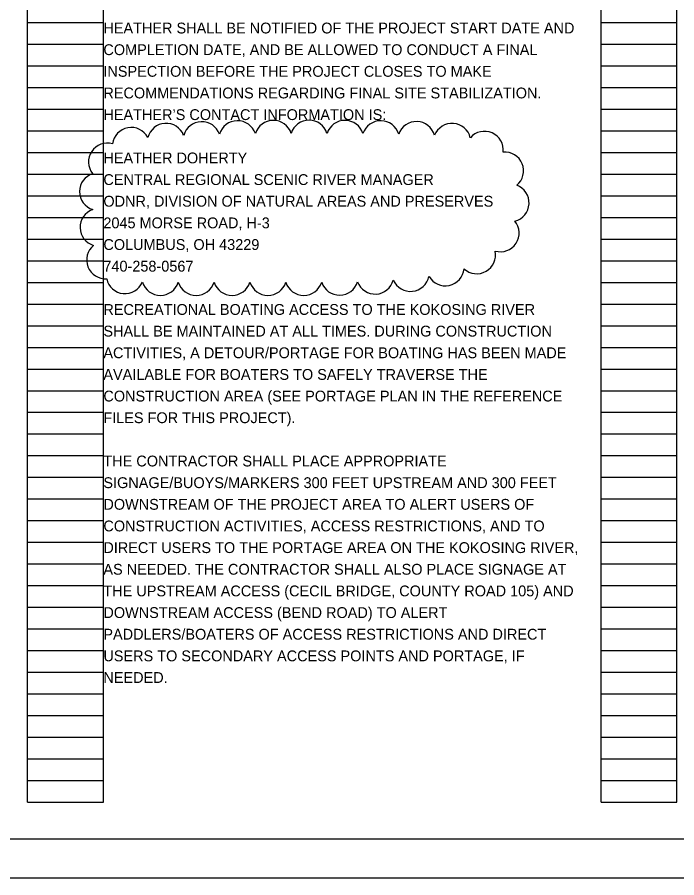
# Model space of a CAD drawing. Extents: x 0 to 58.9, y 0 to 22.
# Drawn here: x 16.12 to 24.66, y 0 to 11.13 of the extents above; entities that cross this region are included whole.
import ezdxf

# ---------------------------------------------------------------- set-up
doc = ezdxf.new("R2010")
doc.units = 0
for name, color, linetype in [('CS-ALGN-CNTR', 7, 'Continuous'), ('CS-ALGN-TEXT', 7, 'Continuous'), ('CS-ANNO-MATC', 7, 'Continuous'), ('CS-ANNO-MATC-MASK', 7, 'Continuous'), ('CS-ANNO-MATC-TEXT', 7, 'Continuous')]:
    doc.layers.add(name, color=color, linetype=linetype)

msp = doc.modelspace()

# ---------------------------------------------------------------- linework, layer by layer
at = {"layer": 'CS-ALGN-CNTR'}
msp.add_lwpolyline([(0, 0), (34, 0), (34, 22), (0, 22)], close=True, dxfattribs=at)
at = {"layer": 'CS-ALGN-TEXT'}
msp.add_lwpolyline([(1.5, 21.5), (33.5, 21.5), (33.5, 0.5), (1.5, 0.5)], close=True, dxfattribs=at)
at = {"layer": 'CS-ANNO-MATC-MASK'}
for p, q in [((16.26, 0.98), (16.26, 21.14)), ((17.24, 0.98), (17.24, 21.14)), ((23.68, 0.98), (23.68, 21.14)), ((24.66, 0.98), (24.66, 21.14)), ((16.26, 11.06), (17.24, 11.06)), ((23.68, 11.06), (24.66, 11.06)), ((16.26, 10.78), (17.24, 10.78)), ((23.68, 10.78), (24.66, 10.78)), ((16.26, 10.5), (17.24, 10.5)), ((23.68, 10.5), (24.66, 10.5)), ((16.26, 10.22), (17.24, 10.22)), ((23.68, 10.22), (24.66, 10.22)), ((16.26, 9.94), (17.24, 9.94)), ((23.68, 9.94), (24.66, 9.94)), ((16.26, 9.66), (17.24, 9.66)), ((23.68, 9.66), (24.66, 9.66)), ((16.26, 9.38), (17.24, 9.38)), ((23.68, 9.38), (24.66, 9.38)), ((16.26, 9.1), (17.24, 9.1)), ((23.68, 9.1), (24.66, 9.1)), ((16.26, 8.82), (17.24, 8.82)), ((23.68, 8.82), (24.66, 8.82)), ((16.26, 8.54), (17.24, 8.54)), ((23.68, 8.54), (24.66, 8.54)), ((16.26, 8.26), (17.24, 8.26)), ((23.68, 8.26), (24.66, 8.26)), ((16.26, 7.98), (17.24, 7.98)), ((23.68, 7.98), (24.66, 7.98)), ((16.26, 7.7), (17.24, 7.7)), ((23.68, 7.7), (24.66, 7.7)), ((16.26, 7.42), (17.24, 7.42)), ((23.68, 7.42), (24.66, 7.42)), ((16.26, 7.14), (17.24, 7.14)), ((23.68, 7.14), (24.66, 7.14)), ((16.26, 6.86), (17.24, 6.86)), ((23.68, 6.86), (24.66, 6.86)), ((16.26, 6.58), (17.24, 6.58)), ((23.68, 6.58), (24.66, 6.58)), ((16.26, 6.3), (17.24, 6.3)), ((23.68, 6.3), (24.66, 6.3)), ((16.26, 6.02), (17.24, 6.02)), ((23.68, 6.02), (24.66, 6.02)), ((16.26, 5.74), (17.24, 5.74)), ((23.68, 5.74), (24.66, 5.74)), ((16.26, 5.46), (17.24, 5.46)), ((23.68, 5.46), (24.66, 5.46)), ((16.26, 5.18), (17.24, 5.18)), ((23.68, 5.18), (24.66, 5.18)), ((16.26, 4.9), (17.24, 4.9)), ((23.68, 4.9), (24.66, 4.9)), ((16.26, 4.62), (17.24, 4.62)), ((23.68, 4.62), (24.66, 4.62)), ((16.26, 4.34), (17.24, 4.34)), ((23.68, 4.34), (24.66, 4.34)), ((16.26, 4.06), (17.24, 4.06)), ((23.68, 4.06), (24.66, 4.06)), ((16.26, 3.78), (17.24, 3.78)), ((23.68, 3.78), (24.66, 3.78)), ((16.26, 3.5), (17.24, 3.5)), ((23.68, 3.5), (24.66, 3.5)), ((16.26, 3.22), (17.24, 3.22)), ((23.68, 3.22), (24.66, 3.22)), ((16.26, 2.94), (17.24, 2.94)), ((23.68, 2.94), (24.66, 2.94)), ((16.26, 2.66), (17.24, 2.66)), ((23.68, 2.66), (24.66, 2.66)), ((16.26, 2.38), (17.24, 2.38)), ((23.68, 2.38), (24.66, 2.38)), ((16.26, 2.1), (17.24, 2.1)), ((23.68, 2.1), (24.66, 2.1)), ((16.26, 1.82), (17.24, 1.82)), ((23.68, 1.82), (24.66, 1.82)), ((16.26, 1.54), (17.24, 1.54)), ((23.68, 1.54), (24.66, 1.54)), ((16.26, 1.26), (17.24, 1.26)), ((23.68, 1.26), (24.66, 1.26)), ((16.26, 0.98), (17.24, 0.98)), ((23.68, 0.98), (24.66, 0.98))]:
    msp.add_line(p, q, dxfattribs=at)
at = {"layer": 'CS-ANNO-MATC-TEXT'}
for centre, start, end in [((19.439, 9.553), 17.8952, 162.8952), ((19.902, 9.555), 17.5108, 162.5108), ((20.366, 9.553), 17.1502, 162.1502), ((17.6, 9.461), 27.6475, 172.6475), ((18.052, 9.515), 21.0256, 166.0256), ((18.513, 9.536), 19.3052, 164.3052), ((18.976, 9.548), 18.4405, 163.4405), ((20.829, 9.548), 16.6279, 161.6279), ((21.291, 9.538), 15.7296, 160.7296), ((21.752, 9.514), 13.4884, 158.4884), ((22.172, 9.411), 353.9182, 138.9182), ((17.291, 9.259), 73.7211, 218.7211), ((22.434, 9.143), 309.7879, 94.7879), ((17.175, 8.875), 107.5, 252.5), ((22.505, 8.728), 284.6035, 69.6035), ((17.181, 8.413), 109.0784, 254.0784), ((22.377, 8.34), 254.0579, 39.0579), ((17.267, 7.99), 128.9316, 273.9316), ((22.072, 8.055), 227.0718, 12.0718), ((21.665, 7.899), 209.7199, 354.7199), ((17.521, 7.798), 192.0378, 337.0378), ((17.978, 7.776), 197.3551, 342.3551), ((18.441, 7.775), 197.5, 342.5), ((18.905, 7.775), 197.5, 342.5), ((19.369, 7.775), 197.5, 342.5), ((19.833, 7.775), 197.5, 342.5), ((20.296, 7.778), 198.2263, 343.2263), ((20.757, 7.792), 200.2598, 345.2598), ((21.215, 7.827), 203.4789, 348.4789)]:
    msp.add_arc(centre, 0.243, start, end, dxfattribs=at)

# ---------------------------------------------------------------- texts
at = {"layer": 'CS-ANNO-MATC'}
for s, p in [('HEATHER SHALL BE NOTIFIED OF THE PROJECT START DATE AND ', (17.24, 10.92)), ('COMPLETION DATE, AND BE ALLOWED TO CONDUCT A FINAL ', (17.24, 10.64)), ('INSPECTION BEFORE THE PROJECT CLOSES TO MAKE ', (17.24, 10.36)), ('RECOMMENDATIONS REGARDING FINAL SITE STABILIZATION. ', (17.24, 10.08)), ('HEATHER’S CONTACT INFORMATION IS:', (17.24, 9.8)), ('HEATHER DOHERTY', (17.24, 9.24)), ('CENTRAL REGIONAL SCENIC RIVER MANAGER', (17.24, 8.96)), ('ODNR, DIVISION OF NATURAL AREAS AND PRESERVES', (17.24, 8.68)), ('2045 MORSE ROAD, H-3', (17.24, 8.4)), ('COLUMBUS, OH 43229', (17.24, 8.12)), ('740-258-0567', (17.24, 7.84)), ('RECREATIONAL BOATING ACCESS TO THE KOKOSING RIVER ', (17.24, 7.28)), ('SHALL BE MAINTAINED AT ALL TIMES. DURING CONSTRUCTION ', (17.24, 7)), ('ACTIVITIES, A DETOUR/PORTAGE FOR BOATING HAS BEEN MADE ', (17.24, 6.72)), ('AVAILABLE FOR BOATERS TO SAFELY TRAVERSE THE ', (17.24, 6.44)), ('CONSTRUCTION AREA (SEE PORTAGE PLAN IN THE REFERENCE ', (17.24, 6.16)), ('FILES FOR THIS PROJECT).', (17.24, 5.88)), ('THE CONTRACTOR SHALL PLACE APPROPRIATE ', (17.24, 5.32)), ('SIGNAGE/BUOYS/MARKERS 300 FEET UPSTREAM AND 300 FEET ', (17.24, 5.04)), ('DOWNSTREAM OF THE PROJECT AREA TO ALERT USERS OF ', (17.24, 4.76)), ('CONSTRUCTION ACTIVITIES, ACCESS RESTRICTIONS, AND TO ', (17.24, 4.48)), ('DIRECT USERS TO THE PORTAGE AREA ON THE KOKOSING RIVER, ', (17.24, 4.2)), ('AS NEEDED. THE CONTRACTOR SHALL ALSO PLACE SIGNAGE AT ', (17.24, 3.92)), ('THE UPSTREAM ACCESS (CECIL BRIDGE, COUNTY ROAD 105) AND ', (17.24, 3.64)), ('DOWNSTREAM ACCESS (BEND ROAD) TO ALERT ', (17.24, 3.36)), ('PADDLERS/BOATERS OF ACCESS RESTRICTIONS AND DIRECT ', (17.24, 3.08)), ('USERS TO SECONDARY ACCESS POINTS AND PORTAGE, IF ', (17.24, 2.8)), ('NEEDED.', (17.24, 2.52))]:
    msp.add_text(s, height=0.14, dxfattribs=at).set_placement(p)

doc.saveas('drawing.dxf')
